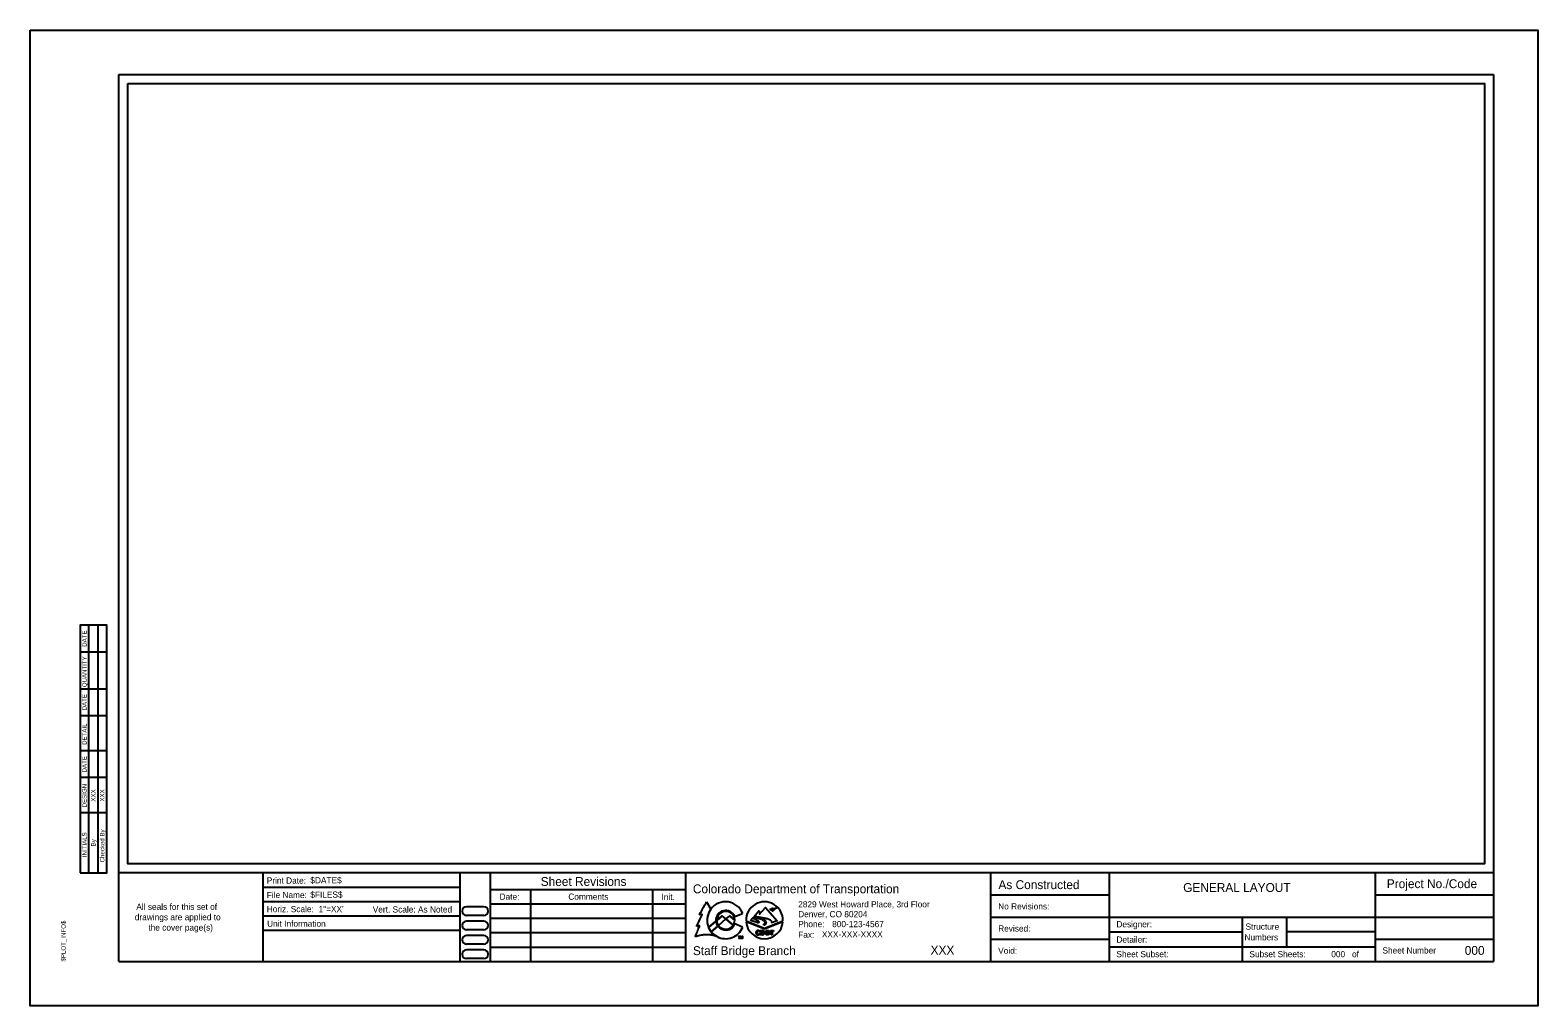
# Model space of a CAD drawing. Extents: x 0 to 17, y 0 to 11.
import ezdxf

# ---------------------------------------------------------------- set-up
doc = ezdxf.new("R2010")
doc.units = 0
for name, color, linetype in [('BRDG_OUTLINE', 7, 'Continuous'), ('DRAFT_Information-No Plot', 7, 'Continuous'), ('DRAFT_Miscellaneous-White', 7, 'Continuous'), ('SHEET_Lines', 7, 'Continuous'), ('SHEET_Plot Boundary', 7, 'Continuous'), ('SHEET_Text-Border Info', 7, 'Continuous'), ('SHEET_Text-Sheet Number', 7, 'Continuous'), ('SHEET_Text-Titles', 7, 'Continuous')]:
    doc.layers.add(name, color=color, linetype=linetype)

msp = doc.modelspace()

# ---------------------------------------------------------------- linework, layer by layer
at = {"layer": 'BRDG_OUTLINE'}
for p, q in [((0.663, 1.5), (0.663, 4.292)), ((0.763, 4.292), (0.763, 1.5)), ((0.563, 3.992), (0.863, 3.992)), ((0.563, 3.575), (0.863, 3.575)), ((0.563, 3.275), (0.863, 3.275)), ((0.863, 2.875), (0.563, 2.875)), ((0.863, 2.575), (0.563, 2.575)), ((0.863, 2.175), (0.563, 2.175))]:
    msp.add_line(p, q, dxfattribs=at)
msp.add_lwpolyline([(0.563, 1.5), (0.863, 1.5), (0.863, 4.292), (0.563, 4.292)], close=True, dxfattribs=at)
at = {"layer": 'DRAFT_Information-No Plot'}
msp.add_line((0, 0), (0, 0), dxfattribs=at)
msp.add_line((0, 0), (0, 0), dxfattribs=at)
msp.add_lwpolyline([(1.1, 10.4), (16.4, 10.4), (16.4, 1.6), (1.1, 1.6)], close=True, dxfattribs=at)
at = {"layer": 'DRAFT_Miscellaneous-White'}
for p, q in [((7.579, 1.034), (7.545, 1.027)), ((7.628, 1.174), (7.676, 1.091)), ((7.946, 1.007), (8.033, 1.042)), ((8.376, 1.083), (8.359, 1.079)), ((7.55, 0.906), (7.516, 0.895)), ((7.65, 0.883), (7.732, 0.954)), ((7.732, 0.954), (7.65, 0.883)), ((7.753, 0.899), (7.679, 0.835)), ((7.679, 0.835), (7.753, 0.899)), ((7.803, 1.016), (7.741, 0.962)), ((7.741, 0.961), (7.803, 1.015)), ((7.845, 0.98), (7.76, 0.906)), ((7.76, 0.906), (7.845, 0.98)), ((7.845, 0.98), (7.803, 1.016)), ((7.803, 1.015), (7.845, 0.979)), ((7.886, 1.016), (7.845, 0.98)), ((7.845, 0.979), (7.886, 1.015)), ((7.927, 0.908), (7.845, 0.98)), ((7.845, 0.98), (7.927, 0.908)), ((7.944, 0.965), (7.886, 1.016)), ((7.886, 1.015), (7.944, 0.965)), ((8.033, 0.888), (7.946, 0.923)), ((8.072, 0.96), (8.28, 0.875)), ((8.28, 0.863), (8.073, 0.948)), ((8.124, 0.964), (8.146, 0.989)), ((8.198, 0.938), (8.124, 0.964)), ((8.152, 0.995), (8.154, 0.998)), ((8.269, 0.914), (8.264, 0.916)), ((8.282, 0.909), (8.277, 0.911)), ((8.28, 0.875), (8.488, 0.96)), ((8.487, 0.948), (8.28, 0.863)), ((7.991, 0.784), (7.991, 0.784)), ((8.007, 0.781), (8.007, 0.781)), ((8.033, 0.761), (8.033, 0.761)), ((8.217, 0.815), (8.226, 0.807)), ((8.226, 0.842), (8.218, 0.834)), ((8.346, 0.838), (8.346, 0.849)), ((8.346, 0.849), (8.38, 0.849)), ((8.357, 0.838), (8.346, 0.838)), ((8.357, 0.799), (8.357, 0.838)), ((8.368, 0.799), (8.357, 0.799)), ((8.38, 0.838), (8.368, 0.838)), ((8.368, 0.838), (8.368, 0.799)), ((8.38, 0.849), (8.38, 0.838))]:
    msp.add_line(p, q, dxfattribs=at)
for points in [[(8.161, 1.005), (8.217, 1.07), (8.233, 1.053), (8.222, 1.032), (8.293, 1.11), (8.422, 0.958), (8.36, 0.937)], [(8.258, 0.799), (8.236, 0.799), (8.236, 0.849), (8.258, 0.849)], [(8.255, 0.838), (8.248, 0.838), (8.248, 0.81), (8.255, 0.81)]]:
    msp.add_lwpolyline(points, dxfattribs=at)
for radius in [0.0255, 0.0137]:
    msp.add_circle((8.314, 0.825), radius, dxfattribs=at)
for centre, radius, start, end in [((7.841, 0.965), 0.208, 21.7587, 203.3886), ((7.841, 0.965), 0.208, 142.5902, 242.6738), ((7.843, 0.965), 0.111, 22.3606, 185.6203), ((7.843, 0.964), 0.101, 0.3586, 181.561), ((8.28, 0.965), 0.208, 358.517, 181.483), ((7.841, 0.965), 0.208, 203.3886, 242.7191), ((7.843, 0.965), 0.111, 185.6203, 215.8725), ((7.843, 0.965), 0.101, 181.561, 215.3766), ((7.841, 0.965), 0.208, 242.7191, 338.2684), ((7.843, 0.965), 0.111, 215.8725, 338.0486), ((7.843, 0.965), 0.101, 215.3766, 326.2328), ((7.843, 0.965), 0.101, 326.2328, 0.3586), ((8.28, 0.965), 0.208, 184.8402, 355.1598), ((8.208, 0.825), 0.0255, 42.6236, 316.6779), ((7.841, 0.965), 0.208, 218.6779, 242.6738), ((7.841, 0.965), 0.208, 218.6779, 242.6738), ((8.208, 0.825), 0.0137, 42.6236, 316.6779), ((8.254, 0.824), 0.0141, 273.2236, 86.7764), ((8.255, 0.824), 0.0248, 276.249, 83.751)]:
    msp.add_arc(centre, radius, start, end, dxfattribs=at)
for points in [[(7.516, 0.895), (7.528, 0.925), (7.573, 1.019), (7.579, 1.034)], [(7.545, 1.027), (7.568, 1.068), (7.6, 1.125), (7.628, 1.174)], [(8.359, 1.079), (8.353, 1.079), (8.352, 1.08), (8.349, 1.083), (8.344, 1.089), (8.344, 1.09), (8.346, 1.091), (8.351, 1.091), (8.353, 1.089), (8.357, 1.087), (8.358, 1.087), (8.36, 1.087), (8.372, 1.091)], [(8.372, 1.091), (8.365, 1.094), (8.362, 1.095), (8.36, 1.097), (8.361, 1.098), (8.364, 1.099), (8.366, 1.1), (8.369, 1.1), (8.371, 1.099), (8.376, 1.097), (8.384, 1.095)], [(8.389, 1.087), (8.382, 1.077), (8.378, 1.071), (8.374, 1.069), (8.371, 1.069), (8.373, 1.075), (8.376, 1.083)], [(8.384, 1.095), (8.392, 1.098), (8.4, 1.101), (8.403, 1.102), (8.406, 1.102), (8.409, 1.102), (8.41, 1.101), (8.41, 1.099), (8.408, 1.096), (8.4, 1.092), (8.389, 1.087)], [(7.499, 0.777), (7.51, 0.806), (7.533, 0.863), (7.55, 0.906)], [(8.146, 0.989), (8.155, 0.986), (8.163, 0.983), (8.176, 0.978), (8.19, 0.971), (8.201, 0.963), (8.208, 0.958), (8.213, 0.951), (8.215, 0.947), (8.216, 0.945), (8.215, 0.94), (8.211, 0.938), (8.21, 0.937), (8.205, 0.935), (8.202, 0.936), (8.2, 0.937), (8.198, 0.938)], [(8.154, 0.998), (8.209, 0.987), (8.256, 0.973), (8.276, 0.964), (8.289, 0.954), (8.297, 0.943), (8.293, 0.921), (8.282, 0.909)], [(8.36, 0.937), (8.363, 0.944), (8.359, 0.956), (8.337, 0.971), (8.304, 0.982), (8.266, 0.99), (8.238, 0.995), (8.191, 1.002), (8.161, 1.005)], [(8.255, 0.971), (8.258, 0.969), (8.261, 0.967), (8.264, 0.965), (8.266, 0.964), (8.268, 0.963), (8.27, 0.962), (8.272, 0.96), (8.274, 0.959), (8.276, 0.958), (8.277, 0.957), (8.278, 0.956), (8.28, 0.954), (8.281, 0.952), (8.283, 0.95), (8.284, 0.948), (8.284, 0.947), (8.285, 0.946), (8.285, 0.945), (8.285, 0.944), (8.286, 0.943), (8.286, 0.941), (8.286, 0.938), (8.286, 0.934), (8.285, 0.933), (8.285, 0.931), (8.283, 0.928), (8.281, 0.925), (8.278, 0.922), (8.275, 0.92), (8.274, 0.918), (8.272, 0.917), (8.27, 0.915), (8.269, 0.914)], [(8.277, 0.911), (8.284, 0.917), (8.291, 0.925), (8.293, 0.93), (8.292, 0.946), (8.29, 0.949), (8.285, 0.954), (8.269, 0.965), (8.255, 0.971)], [(7.745, 0.78), (7.715, 0.79), (7.667, 0.799), (7.632, 0.801), (7.607, 0.8), (7.552, 0.793), (7.499, 0.777)]]:
    msp.add_spline(points, degree=3, dxfattribs=at)
for points in [[(8.264, 0.916), (8.32, 0.953), (8.234, 0.98), (8.152, 0.995)], [(7.99, 0.782), (7.99, 0.783), (7.99, 0.784)], [(7.99, 0.784), (7.99, 0.784), (7.991, 0.784)], [(7.99, 0.781), (7.99, 0.782), (7.99, 0.782)], [(7.996, 0.781), (7.992, 0.78), (7.99, 0.78)], [(7.99, 0.78), (7.99, 0.78), (7.99, 0.781)], [(7.99, 0.781), (7.99, 0.781), (7.99, 0.781)], [(7.991, 0.784), (7.997, 0.784), (7.999, 0.784)], [(7.997, 0.773), (7.997, 0.775), (7.996, 0.781)], [(7.996, 0.767), (7.997, 0.771), (7.997, 0.773)], [(7.996, 0.761), (7.996, 0.763), (7.996, 0.767)], [(7.997, 0.761), (7.996, 0.761), (7.996, 0.761)], [(7.998, 0.761), (7.997, 0.761), (7.997, 0.761)], [(7.999, 0.761), (7.999, 0.761), (7.998, 0.761)], [(7.998, 0.761), (7.998, 0.761), (7.998, 0.761)], [(7.999, 0.784), (8, 0.784), (8.004, 0.784)], [(8, 0.761), (8, 0.761), (7.999, 0.761)], [(8.001, 0.761), (8.001, 0.761), (8, 0.761)], [(8.007, 0.781), (8.006, 0.781), (8.001, 0.781)], [(8.001, 0.781), (8.001, 0.776), (8.001, 0.773)], [(8.001, 0.773), (8.001, 0.771), (8.001, 0.767)], [(8.001, 0.767), (8.001, 0.763), (8.001, 0.761)], [(8.004, 0.784), (8.007, 0.784), (8.006, 0.784)], [(8.006, 0.784), (8.007, 0.784), (8.007, 0.784)], [(8.007, 0.784), (8.007, 0.784), (8.007, 0.782)], [(8.007, 0.782), (8.007, 0.782), (8.007, 0.782)], [(8.007, 0.782), (8.007, 0.781), (8.007, 0.781)], [(8.007, 0.781), (8.007, 0.781), (8.007, 0.781)], [(8.009, 0.778), (8.009, 0.782), (8.009, 0.784)], [(8.009, 0.784), (8.009, 0.784), (8.009, 0.784)], [(8.009, 0.784), (8.012, 0.784), (8.013, 0.784)], [(8.009, 0.772), (8.009, 0.774), (8.009, 0.778)], [(8.009, 0.766), (8.009, 0.77), (8.009, 0.772)], [(8.009, 0.761), (8.009, 0.763), (8.009, 0.766)], [(8.01, 0.761), (8.01, 0.761), (8.009, 0.761)], [(8.009, 0.761), (8.009, 0.761), (8.009, 0.761)], [(8.011, 0.761), (8.011, 0.761), (8.01, 0.761)], [(8.012, 0.761), (8.011, 0.761), (8.011, 0.761)], [(8.013, 0.761), (8.013, 0.761), (8.012, 0.761)], [(8.013, 0.784), (8.013, 0.784), (8.013, 0.784)], [(8.013, 0.784), (8.017, 0.775), (8.02, 0.768)], [(8.014, 0.774), (8.014, 0.774), (8.013, 0.774)], [(8.013, 0.774), (8.013, 0.774), (8.013, 0.774)], [(8.013, 0.774), (8.013, 0.772), (8.013, 0.768)], [(8.013, 0.768), (8.013, 0.763), (8.013, 0.761)], [(8.013, 0.761), (8.013, 0.761), (8.013, 0.761)], [(8.018, 0.764), (8.016, 0.768), (8.014, 0.774)], [(8.019, 0.761), (8.019, 0.762), (8.018, 0.764)], [(8.021, 0.76), (8.02, 0.76), (8.019, 0.761)], [(8.02, 0.768), (8.021, 0.766), (8.021, 0.766)], [(8.021, 0.766), (8.021, 0.766), (8.022, 0.767)], [(8.022, 0.76), (8.022, 0.76), (8.021, 0.76)], [(8.022, 0.767), (8.024, 0.773), (8.028, 0.784)], [(8.024, 0.764), (8.023, 0.763), (8.022, 0.76)], [(8.028, 0.774), (8.027, 0.772), (8.024, 0.764)], [(8.028, 0.784), (8.028, 0.784), (8.029, 0.784)], [(8.028, 0.768), (8.028, 0.772), (8.028, 0.774)], [(8.028, 0.774), (8.028, 0.774), (8.028, 0.774)], [(8.028, 0.774), (8.028, 0.774), (8.028, 0.774)], [(8.028, 0.761), (8.028, 0.763), (8.028, 0.768)], [(8.029, 0.761), (8.029, 0.761), (8.028, 0.761)], [(8.028, 0.761), (8.028, 0.761), (8.028, 0.761)], [(8.029, 0.784), (8.029, 0.784), (8.03, 0.784)], [(8.03, 0.761), (8.03, 0.761), (8.029, 0.761)], [(8.03, 0.784), (8.032, 0.784), (8.032, 0.784)], [(8.031, 0.761), (8.031, 0.761), (8.03, 0.761)], [(8.032, 0.761), (8.032, 0.761), (8.031, 0.761)], [(8.032, 0.784), (8.033, 0.784), (8.033, 0.784)], [(8.033, 0.784), (8.033, 0.782), (8.032, 0.778)], [(8.032, 0.778), (8.032, 0.774), (8.032, 0.772)], [(8.032, 0.772), (8.032, 0.77), (8.032, 0.767)], [(8.032, 0.767), (8.033, 0.763), (8.033, 0.761)], [(8.033, 0.761), (8.033, 0.761), (8.032, 0.761)]]:
    msp.add_open_spline(points, degree=2, dxfattribs=at)
at = {"layer": 'SHEET_Lines'}
for p, q in [((1, 10.5), (16.5, 10.5)), ((1, 0.5), (1, 10.5)), ((16.5, 10.5), (16.5, 0.5)), ((16.5, 1.5), (1, 1.5)), ((2.625, 1.5), (2.625, 0.5)), ((4.85, 0.5), (4.85, 1.5)), ((5.189, 0.5), (5.189, 1.5)), ((7.392, 0.5), (7.392, 1.5)), ((10.833, 0.5), (10.833, 1.5)), ((12.167, 1.5), (12.167, 0.5)), ((15.167, 1.5), (15.167, 0.5)), ((2.625, 1.338), (4.85, 1.338)), ((5.189, 1.313), (7.392, 1.313)), ((5.647, 0.5), (5.647, 1.313)), ((7.022, 0.5), (7.022, 1.313)), ((10.833, 1.25), (12.167, 1.25)), ((15.167, 1.25), (16.5, 1.25)), ((2.625, 1.175), (4.85, 1.175)), ((5.116, 1.118), (4.92, 1.118)), ((5.189, 1.15), (7.392, 1.15)), ((2.625, 1.013), (4.85, 1.013)), ((4.85, 0.85), (2.625, 0.85)), ((5.116, 1.02), (4.92, 1.02)), ((5.116, 0.955), (4.92, 0.955)), ((5.116, 0.857), (4.92, 0.857)), ((5.189, 0.988), (7.392, 0.988)), ((10.833, 1), (16.5, 1)), ((13.667, 1), (13.667, 0.5)), ((14.167, 1), (14.167, 0.667)), ((5.116, 0.793), (4.92, 0.793)), ((5.116, 0.695), (4.92, 0.695)), ((5.189, 0.825), (7.392, 0.825)), ((10.833, 0.75), (12.167, 0.75)), ((12.167, 0.833), (13.667, 0.833)), ((15.167, 0.833), (14.167, 0.833)), ((15.167, 0.75), (16.5, 0.75)), ((5.116, 0.63), (4.92, 0.63)), ((5.116, 0.532), (4.92, 0.532)), ((5.189, 0.663), (7.392, 0.663)), ((12.167, 0.667), (15.167, 0.667)), ((1, 0.5), (16.5, 0.5))]:
    msp.add_line(p, q, dxfattribs=at)
for centre, start, end in [((4.92, 1.069), 90, 270), ((5.116, 1.069), 270, 90), ((4.92, 0.906), 90, 270), ((5.116, 0.906), 270, 90), ((4.92, 0.744), 90, 270), ((5.116, 0.744), 270, 90), ((4.92, 0.581), 90, 270), ((5.116, 0.581), 270, 90)]:
    msp.add_arc(centre, 0.0491, start, end, dxfattribs=at)
at = {"layer": 'SHEET_Plot Boundary'}
msp.add_lwpolyline([(0, 11), (17, 11), (17, 0), (0, 0)], close=True, dxfattribs=at)

# ---------------------------------------------------------------- texts
at = {"layer": 'SHEET_Text-Border Info'}
for s, p in [('DATE', (0.637, 4.048)), ('QUANTITY', (0.637, 3.592)), ('DATE', (0.637, 3.331)), ('DETAIL', (0.637, 2.942)), ('DATE', (0.637, 2.631)), ('DESIGN', (0.637, 2.237)), ('XXX', (0.737, 2.303)), ('XXX', (0.837, 2.303)), ('INITIALS', (0.637, 1.676)), ('By', (0.737, 1.798)), ('Checked By', (0.837, 1.617)), ('$PLOT_INFO$', (0.4, 0.5))]:
    msp.add_text(s, height=0.05, rotation=90, dxfattribs=at).set_placement(p)
for s, p in [('Print Date:', (2.668, 1.378)), ('$DATE$', (3.159, 1.381)), ('File Name:', (2.668, 1.215)), ('$FILES$', (3.159, 1.219)), ('Date:', (5.293, 1.196)), ('Comments', (6.068, 1.196)), ('Init.', (7.119, 1.193)), ('drawings are applied to', (1.18, 0.965)), ('All seals for this set of', (1.197, 1.082)), ('Horiz. Scale:', (2.668, 1.056)), ('1"=XX\'', (3.252, 1.056)), ('1"=XX\'', (3.252, 1.056)), ('Vert. Scale: As Noted', (3.863, 1.052)), ('2829 West Howard Place, 3rd Floor', (8.66, 1.11)), ('Denver, CO 80204', (8.66, 0.999)), ('No Revisions:', (10.915, 1.087)), ('the cover page(s)', (1.333, 0.848)), ('Unit Information', (2.672, 0.892)), ('Phone:', (8.66, 0.887)), ('800-123-4567', (9.043, 0.887)), ('Revised:', (10.915, 0.837)), ('Designer:', (12.248, 0.885)), ('Structure', (13.704, 0.858)), ('Fax:', (8.66, 0.767)), ('XXX-XXX-XXXX', (8.927, 0.771)), ('Detailer:', (12.248, 0.712)), ('Numbers', (13.692, 0.738)), ('Void:', (10.915, 0.587)), ('Sheet Subset:', (12.248, 0.548)), ('Subset Sheets:', (13.748, 0.548)), ('000', (14.671, 0.548)), ('000', (14.671, 0.548)), (' of ', (14.879, 0.548)), (' of ', (14.879, 0.548)), ('Sheet Number', (15.248, 0.59))]:
    msp.add_text(s, height=0.07, dxfattribs=at).set_placement(p)
at = {"layer": 'SHEET_Text-Sheet Number'}
msp.add_text('000', height=0.1, dxfattribs=at).set_placement((16.176, 0.575))
msp.add_text('000', height=0.1, dxfattribs=at).set_placement((16.176, 0.575))
at = {"layer": 'SHEET_Text-Titles'}
for s, p in [('Sheet Revisions', (5.757, 1.352)), ('Colorado Department of Transportation', (7.473, 1.269)), ('As Constructed', (10.918, 1.316)), ('GENERAL LAYOUT', (13.001, 1.284)), ('Project No./Code', (15.297, 1.327)), ('Staff Bridge Branch ', (7.473, 0.572)), ('XXX', (10.153, 0.578))]:
    msp.add_text(s, height=0.1, dxfattribs=at).set_placement(p)

doc.saveas('drawing.dxf')
